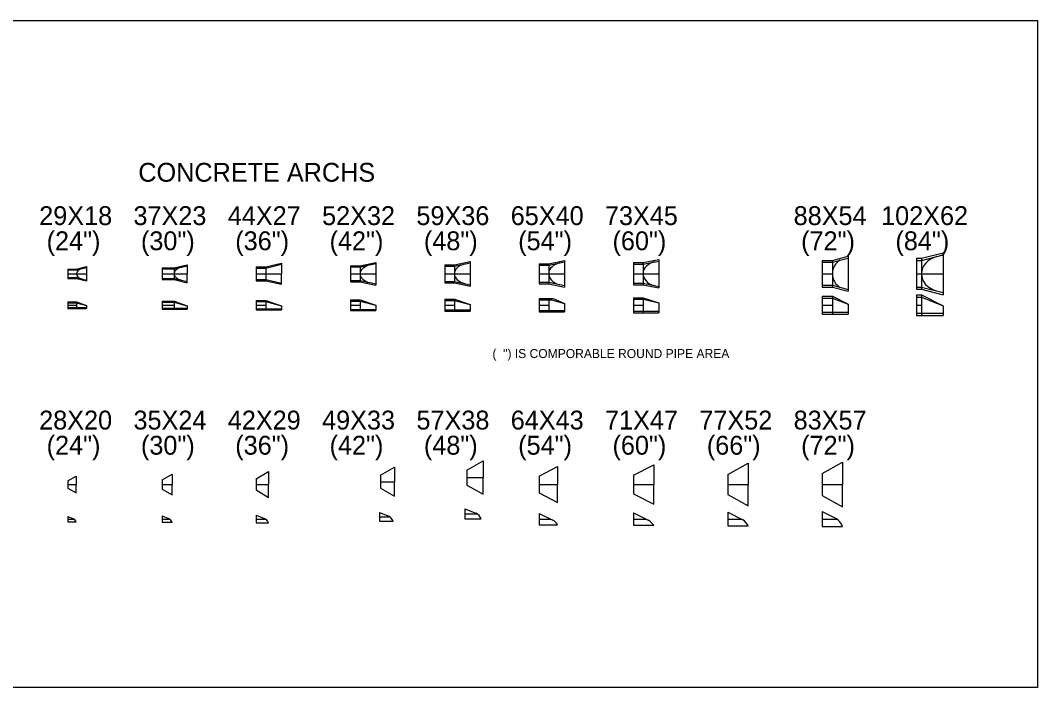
# Model space of a CAD drawing. Extents: x 20500915 to 20506562, y 7965868 to 7970770.
# Drawn here: x 20501230.9 to 20501554.5, y 7966058.6 to 7966270.8 of the extents above; entities that cross this region are included whole.
import ezdxf

# ---------------------------------------------------------------- set-up
doc = ezdxf.new("R2010")
doc.units = 0
doc.layers.add('brgPreStructureNew', color=7, linetype='Continuous')

msp = doc.modelspace()

# ---------------------------------------------------------------- linework, layer by layer
at = {"layer": 'brgPreStructureNew'}
for p, q in [((20501398.93, 7966193.4), (20501403.93, 7966194.44)), ((20501403.93, 7966194.44), (20501403.93, 7966186.02)), ((20501428.93, 7966193.77), (20501433.93, 7966194.73)), ((20501433.93, 7966194.73), (20501433.93, 7966185.73)), ((20501485.93, 7966194.48), (20501485.93, 7966185.98)), ((20501485.93, 7966194.48), (20501489.18, 7966194.48)), ((20501489.18, 7966194.48), (20501494.18, 7966195.81)), ((20501489.18, 7966193.9), (20501494.18, 7966195.23)), ((20501489.18, 7966194.48), (20501489.18, 7966185.98)), ((20501494.18, 7966195.81), (20501494.18, 7966184.65)), ((20501515.93, 7966195.15), (20501515.93, 7966185.31)), ((20501515.93, 7966195.15), (20501517.52, 7966195.15)), ((20501515.93, 7966194.48), (20501517.52, 7966194.48)), ((20501517.52, 7966195.15), (20501524.43, 7966196.9)), ((20501517.52, 7966194.48), (20501524.43, 7966196.23)), ((20501517.52, 7966195.15), (20501517.52, 7966185.31)), ((20501524.43, 7966196.9), (20501524.43, 7966183.56)), ((20501245.93, 7966191.73), (20501248.68, 7966191.73)), ((20501245.93, 7966191.73), (20501245.93, 7966188.73)), ((20501245.93, 7966191.44), (20501248.68, 7966191.44)), ((20501248.68, 7966191.73), (20501251.93, 7966192.52)), ((20501248.68, 7966191.44), (20501251.93, 7966192.23)), ((20501251.93, 7966192.52), (20501251.93, 7966187.94)), ((20501275.93, 7966192.1), (20501275.93, 7966188.36)), ((20501275.93, 7966192.1), (20501279.77, 7966192.1)), ((20501275.93, 7966191.77), (20501279.77, 7966191.77)), ((20501279.77, 7966192.1), (20501283.93, 7966193.06)), ((20501279.77, 7966191.77), (20501283.93, 7966192.73)), ((20501279.77, 7966192.1), (20501279.77, 7966188.36)), ((20501283.93, 7966193.06), (20501283.93, 7966190.23)), ((20501305.93, 7966192.44), (20501305.93, 7966188.02)), ((20501305.93, 7966192.44), (20501308.93, 7966192.44)), ((20501305.93, 7966192.06), (20501308.93, 7966192.06)), ((20501308.93, 7966192.44), (20501313.93, 7966193.58)), ((20501308.93, 7966192.06), (20501313.93, 7966193.23)), ((20501308.93, 7966192.44), (20501308.93, 7966188.02)), ((20501313.93, 7966193.58), (20501313.93, 7966190.23)), ((20501335.93, 7966192.77), (20501335.93, 7966187.69)), ((20501335.93, 7966192.77), (20501338.93, 7966192.77)), ((20501335.93, 7966192.4), (20501338.93, 7966192.4)), ((20501338.93, 7966192.77), (20501343.93, 7966193.86)), ((20501338.93, 7966192.4), (20501343.93, 7966193.48)), ((20501338.93, 7966192.77), (20501338.93, 7966187.69)), ((20501343.93, 7966193.86), (20501343.93, 7966186.61)), ((20501365.93, 7966193.11), (20501365.93, 7966187.36)), ((20501365.93, 7966193.11), (20501368.93, 7966193.11)), ((20501365.93, 7966192.69), (20501368.93, 7966192.69)), ((20501368.93, 7966193.11), (20501373.93, 7966194.15)), ((20501368.93, 7966192.69), (20501373.93, 7966193.73)), ((20501368.93, 7966193.11), (20501368.93, 7966187.36)), ((20501373.93, 7966194.15), (20501373.93, 7966186.31)), ((20501395.93, 7966193.4), (20501395.93, 7966187.06)), ((20501395.93, 7966193.4), (20501398.93, 7966193.4)), ((20501395.93, 7966192.94), (20501398.93, 7966192.94)), ((20501398.93, 7966192.94), (20501403.93, 7966193.98)), ((20501398.93, 7966193.4), (20501398.93, 7966187.06)), ((20501425.93, 7966193.77), (20501425.93, 7966186.69)), ((20501425.93, 7966193.77), (20501428.93, 7966193.77)), ((20501425.93, 7966193.27), (20501428.93, 7966193.27)), ((20501428.93, 7966193.27), (20501433.93, 7966194.23)), ((20501428.93, 7966193.77), (20501428.93, 7966186.69)), ((20501485.93, 7966193.9), (20501489.18, 7966193.9)), ((20501245.93, 7966190.23), (20501251.93, 7966190.23)), ((20501245.93, 7966189.02), (20501248.68, 7966189.02)), ((20501245.93, 7966188.73), (20501248.68, 7966188.73)), ((20501248.68, 7966189.02), (20501251.93, 7966188.23)), ((20501248.68, 7966188.73), (20501251.93, 7966187.94)), ((20501275.93, 7966190.23), (20501283.93, 7966190.23)), ((20501275.93, 7966188.69), (20501279.77, 7966188.69)), ((20501275.93, 7966188.36), (20501279.77, 7966188.36)), ((20501279.77, 7966188.69), (20501283.93, 7966187.73)), ((20501279.77, 7966188.36), (20501283.93, 7966187.4)), ((20501283.93, 7966187.4), (20501283.93, 7966190.23)), ((20501305.93, 7966190.23), (20501313.93, 7966190.23)), ((20501305.93, 7966188.4), (20501308.93, 7966188.4)), ((20501305.93, 7966188.02), (20501308.93, 7966188.02)), ((20501308.93, 7966188.4), (20501313.93, 7966187.23)), ((20501308.93, 7966188.02), (20501313.93, 7966186.88)), ((20501313.93, 7966186.88), (20501313.93, 7966190.23)), ((20501335.93, 7966190.23), (20501343.93, 7966190.23)), ((20501335.93, 7966188.06), (20501338.93, 7966188.06)), ((20501338.93, 7966188.06), (20501343.93, 7966186.98)), ((20501365.93, 7966190.23), (20501373.93, 7966190.23)), ((20501395.93, 7966190.23), (20501403.93, 7966190.23)), ((20501425.93, 7966190.23), (20501433.93, 7966190.23)), ((20501485.93, 7966190.23), (20501489.18, 7966190.23)), ((20501515.93, 7966190.23), (20501524.43, 7966190.23)), ((20501335.93, 7966187.69), (20501338.93, 7966187.69)), ((20501338.93, 7966187.69), (20501343.93, 7966186.61)), ((20501365.93, 7966187.77), (20501368.93, 7966187.77)), ((20501365.93, 7966187.36), (20501368.93, 7966187.36)), ((20501368.93, 7966187.77), (20501373.93, 7966186.73)), ((20501368.93, 7966187.36), (20501373.93, 7966186.31)), ((20501395.93, 7966187.52), (20501398.93, 7966187.52)), ((20501395.93, 7966187.06), (20501398.93, 7966187.06)), ((20501398.93, 7966187.52), (20501403.93, 7966186.48)), ((20501398.93, 7966187.06), (20501403.93, 7966186.02)), ((20501425.93, 7966187.19), (20501428.93, 7966187.19)), ((20501425.93, 7966186.69), (20501428.93, 7966186.69)), ((20501428.93, 7966187.19), (20501433.93, 7966186.23)), ((20501428.93, 7966186.69), (20501433.93, 7966185.73)), ((20501485.93, 7966186.56), (20501489.18, 7966186.56)), ((20501485.93, 7966185.98), (20501489.18, 7966185.98)), ((20501489.18, 7966186.56), (20501494.18, 7966185.23)), ((20501489.18, 7966185.98), (20501494.18, 7966184.65)), ((20501515.93, 7966185.98), (20501517.52, 7966185.98)), ((20501515.93, 7966185.31), (20501517.52, 7966185.31)), ((20501517.52, 7966185.98), (20501524.43, 7966184.23)), ((20501517.52, 7966185.31), (20501524.43, 7966183.56)), ((20501275.93, 7966181.52), (20501275.93, 7966178.94)), ((20501275.93, 7966181.52), (20501279.77, 7966181.52)), ((20501279.77, 7966181.52), (20501279.77, 7966178.94)), ((20501279.77, 7966181.52), (20501283.93, 7966180.07)), ((20501305.93, 7966181.73), (20501305.93, 7966178.73)), ((20501305.93, 7966181.73), (20501308.93, 7966181.73)), ((20501305.93, 7966181.36), (20501308.93, 7966181.36)), ((20501308.93, 7966181.73), (20501308.93, 7966178.73)), ((20501308.93, 7966181.73), (20501313.93, 7966180.03)), ((20501308.93, 7966181.36), (20501313.93, 7966180.03)), ((20501335.93, 7966181.94), (20501335.93, 7966178.52)), ((20501335.93, 7966181.94), (20501338.93, 7966181.94)), ((20501335.93, 7966181.56), (20501338.93, 7966181.56)), ((20501338.93, 7966181.94), (20501343.93, 7966180.22)), ((20501338.93, 7966181.56), (20501338.93, 7966178.52)), ((20501338.93, 7966181.56), (20501343.93, 7966180.22)), ((20501365.93, 7966182.15), (20501365.93, 7966178.31)), ((20501365.93, 7966182.15), (20501368.93, 7966182.15)), ((20501365.93, 7966181.73), (20501368.93, 7966181.73)), ((20501368.93, 7966182.15), (20501368.93, 7966178.31)), ((20501368.93, 7966182.15), (20501373.93, 7966180.48)), ((20501368.93, 7966181.73), (20501373.93, 7966180.48)), ((20501395.93, 7966182.36), (20501395.93, 7966178.11)), ((20501395.93, 7966182.36), (20501400.27, 7966182.36)), ((20501395.93, 7966181.9), (20501399.86, 7966181.9)), ((20501398.93, 7966182.36), (20501398.93, 7966178.11)), ((20501399.86, 7966181.9), (20501403.93, 7966180.78)), ((20501400.35, 7966182.36), (20501403.93, 7966180.78)), ((20501425.93, 7966182.61), (20501425.93, 7966177.86)), ((20501425.93, 7966182.61), (20501428.93, 7966182.61)), ((20501425.93, 7966182.11), (20501428.93, 7966182.11)), ((20501428.93, 7966182.61), (20501428.93, 7966177.86)), ((20501428.93, 7966182.61), (20501433.93, 7966180.94)), ((20501428.93, 7966182.11), (20501433.93, 7966180.94)), ((20501485.93, 7966183.06), (20501485.93, 7966177.4)), ((20501485.93, 7966183.06), (20501489.18, 7966183.06)), ((20501485.93, 7966182.48), (20501489.18, 7966182.48)), ((20501489.18, 7966183.06), (20501489.18, 7966177.4)), ((20501489.18, 7966183.06), (20501494.18, 7966180.56)), ((20501489.18, 7966182.48), (20501494.18, 7966180.56)), ((20501515.93, 7966183.48), (20501515.93, 7966176.98)), ((20501515.93, 7966183.48), (20501517.52, 7966183.48)), ((20501515.93, 7966182.81), (20501517.52, 7966182.81)), ((20501517.52, 7966183.48), (20501517.52, 7966176.98)), ((20501517.52, 7966183.48), (20501524.43, 7966180.02)), ((20501517.52, 7966182.81), (20501524.43, 7966180.02)), ((20501245.93, 7966181.27), (20501248.68, 7966181.27)), ((20501245.93, 7966181.27), (20501245.93, 7966179.19)), ((20501245.93, 7966180.98), (20501248.68, 7966180.98)), ((20501245.93, 7966180.23), (20501248.68, 7966180.23)), ((20501245.93, 7966179.48), (20501251.93, 7966179.48)), ((20501245.93, 7966179.19), (20501251.93, 7966179.19)), ((20501248.68, 7966181.27), (20501251.93, 7966180.19)), ((20501248.68, 7966181.27), (20501248.68, 7966179.19)), ((20501248.68, 7966180.98), (20501251.93, 7966180.19)), ((20501251.93, 7966180.19), (20501251.93, 7966179.19)), ((20501275.93, 7966181.19), (20501279.77, 7966181.19)), ((20501275.93, 7966180.23), (20501279.77, 7966180.23)), ((20501275.93, 7966179.27), (20501283.93, 7966179.27)), ((20501275.93, 7966178.94), (20501283.93, 7966178.94)), ((20501279.77, 7966181.19), (20501283.93, 7966180.07)), ((20501283.93, 7966180.07), (20501283.93, 7966178.94)), ((20501305.93, 7966180.23), (20501308.93, 7966180.23)), ((20501305.93, 7966179.11), (20501313.93, 7966179.11)), ((20501305.93, 7966178.73), (20501313.93, 7966178.73)), ((20501313.93, 7966180.03), (20501313.93, 7966178.73)), ((20501335.93, 7966180.23), (20501338.93, 7966180.23)), ((20501335.93, 7966178.9), (20501338.93, 7966178.9)), ((20501335.93, 7966178.52), (20501338.93, 7966178.52)), ((20501338.93, 7966178.9), (20501343.93, 7966178.9)), ((20501338.93, 7966178.52), (20501343.93, 7966178.52)), ((20501343.93, 7966180.22), (20501343.93, 7966178.52)), ((20501365.93, 7966180.23), (20501368.93, 7966180.23)), ((20501365.93, 7966178.73), (20501368.93, 7966178.73)), ((20501365.93, 7966178.31), (20501368.93, 7966178.31)), ((20501368.93, 7966178.73), (20501373.93, 7966178.73)), ((20501368.93, 7966178.31), (20501373.93, 7966178.31)), ((20501373.93, 7966180.48), (20501373.93, 7966178.31)), ((20501395.93, 7966180.23), (20501398.93, 7966180.23)), ((20501395.93, 7966178.56), (20501399.94, 7966178.56)), ((20501395.93, 7966178.11), (20501400.11, 7966178.11)), ((20501399.94, 7966178.56), (20501403.93, 7966178.56)), ((20501400.11, 7966178.11), (20501403.93, 7966178.11)), ((20501403.93, 7966180.78), (20501403.93, 7966178.11)), ((20501425.93, 7966180.23), (20501428.93, 7966180.23)), ((20501425.93, 7966178.36), (20501428.93, 7966178.36)), ((20501428.93, 7966178.36), (20501433.93, 7966178.36)), ((20501433.93, 7966180.94), (20501433.93, 7966177.86)), ((20501485.93, 7966180.23), (20501489.18, 7966180.23)), ((20501494.18, 7966180.56), (20501494.18, 7966177.4)), ((20501515.93, 7966180.23), (20501517.52, 7966180.23)), ((20501524.43, 7966180.02), (20501524.43, 7966176.98)), ((20501425.93, 7966177.86), (20501428.93, 7966177.86)), ((20501428.93, 7966177.86), (20501433.93, 7966177.86)), ((20501485.93, 7966177.98), (20501489.18, 7966177.98)), ((20501485.93, 7966177.4), (20501489.18, 7966177.4)), ((20501489.18, 7966177.98), (20501494.18, 7966177.98)), ((20501489.18, 7966177.4), (20501494.18, 7966177.4)), ((20501515.93, 7966177.65), (20501517.52, 7966177.65)), ((20501515.93, 7966176.98), (20501517.52, 7966176.98)), ((20501517.52, 7966177.65), (20501524.43, 7966177.65)), ((20501517.52, 7966176.98), (20501524.43, 7966176.98)), ((20501372.91, 7966127.8), (20501378.08, 7966130.72)), ((20501378.08, 7966130.72), (20501378.08, 7966125.43)), ((20501455.93, 7966126.44), (20501462.35, 7966129.98)), ((20501462.35, 7966129.98), (20501462.35, 7966123.23)), ((20501485.93, 7966126.69), (20501492.35, 7966130.36)), ((20501492.35, 7966130.36), (20501492.35, 7966123.23)), ((20501275.93, 7966124.69), (20501279.18, 7966126.56)), ((20501279.18, 7966126.56), (20501279.18, 7966123.23)), ((20501305.93, 7966124.98), (20501309.76, 7966127.36)), ((20501309.76, 7966127.36), (20501309.76, 7966123.23)), ((20501345.42, 7966126.16), (20501349.83, 7966128.74)), ((20501349.83, 7966128.74), (20501349.83, 7966124.11)), ((20501372.91, 7966127.8), (20501372.91, 7966123.05)), ((20501395.93, 7966125.9), (20501401.68, 7966128.98)), ((20501401.68, 7966128.98), (20501401.68, 7966123.23)), ((20501425.93, 7966126.19), (20501432.35, 7966129.52)), ((20501432.35, 7966129.52), (20501432.35, 7966123.23)), ((20501455.93, 7966126.44), (20501455.93, 7966120.02)), ((20501485.93, 7966126.69), (20501485.93, 7966119.77)), ((20501245.93, 7966124.4), (20501248.6, 7966125.9)), ((20501245.93, 7966124.4), (20501245.93, 7966122.06)), ((20501245.93, 7966123.23), (20501248.6, 7966123.23)), ((20501248.6, 7966125.9), (20501248.6, 7966123.23)), ((20501248.6, 7966120.56), (20501248.6, 7966123.23)), ((20501275.93, 7966124.69), (20501275.93, 7966121.77)), ((20501275.93, 7966123.23), (20501279.18, 7966123.23)), ((20501279.18, 7966119.9), (20501279.18, 7966123.23)), ((20501305.93, 7966124.98), (20501305.93, 7966121.48)), ((20501305.93, 7966123.23), (20501309.76, 7966123.23)), ((20501309.76, 7966119.11), (20501309.76, 7966123.23)), ((20501345.42, 7966126.16), (20501345.42, 7966122.07)), ((20501345.42, 7966124.11), (20501349.83, 7966124.11)), ((20501349.83, 7966119.49), (20501349.83, 7966124.11)), ((20501372.91, 7966125.43), (20501378.08, 7966125.43)), ((20501378.08, 7966120.14), (20501378.08, 7966125.43)), ((20501395.93, 7966125.9), (20501395.93, 7966120.56)), ((20501395.93, 7966123.23), (20501401.68, 7966123.23)), ((20501401.68, 7966117.48), (20501401.68, 7966123.23)), ((20501425.93, 7966126.19), (20501425.93, 7966120.27)), ((20501425.93, 7966123.23), (20501432.35, 7966123.23)), ((20501432.35, 7966116.94), (20501432.35, 7966123.23)), ((20501455.93, 7966123.23), (20501462.35, 7966123.23)), ((20501462.35, 7966116.48), (20501462.35, 7966123.23)), ((20501485.93, 7966123.23), (20501492.35, 7966123.23)), ((20501492.35, 7966116.11), (20501492.35, 7966123.23)), ((20501245.93, 7966122.06), (20501248.6, 7966120.56)), ((20501275.93, 7966121.77), (20501279.18, 7966119.9)), ((20501305.93, 7966121.48), (20501309.76, 7966119.11)), ((20501345.42, 7966122.07), (20501349.83, 7966119.49)), ((20501372.91, 7966123.05), (20501378.08, 7966120.14)), ((20501395.93, 7966120.56), (20501401.68, 7966117.48)), ((20501425.93, 7966120.27), (20501432.35, 7966116.94)), ((20501455.93, 7966120.02), (20501462.35, 7966116.48)), ((20501485.93, 7966119.77), (20501492.35, 7966116.11)), ((20501305.93, 7966113.44), (20501305.93, 7966111.02)), ((20501305.93, 7966113.44), (20501308.43, 7966112.44)), ((20501345.09, 7966114.35), (20501345.09, 7966111.6)), ((20501345.09, 7966114.35), (20501347.59, 7966113.35)), ((20501372.26, 7966115.47), (20501372.26, 7966112.31)), ((20501372.26, 7966115.47), (20501375.73, 7966114.08)), ((20501372.26, 7966113.89), (20501376.12, 7966113.89)), ((20501395.93, 7966114.02), (20501395.93, 7966110.44)), ((20501395.93, 7966114.02), (20501400.21, 7966111.88)), ((20501425.93, 7966114.19), (20501425.93, 7966110.27)), ((20501425.93, 7966114.19), (20501430.59, 7966111.86)), ((20501455.93, 7966114.4), (20501455.93, 7966110.06)), ((20501455.93, 7966114.4), (20501460.7, 7966112.02)), ((20501485.93, 7966114.61), (20501485.93, 7966109.86)), ((20501485.93, 7966114.61), (20501490.33, 7966112.41)), ((20501245.93, 7966113.06), (20501245.93, 7966111.4)), ((20501245.93, 7966113.06), (20501247.56, 7966112.41)), ((20501245.93, 7966112.23), (20501247.87, 7966112.23)), ((20501245.93, 7966111.4), (20501248.6, 7966111.4)), ((20501275.93, 7966113.23), (20501275.93, 7966111.23)), ((20501275.93, 7966113.23), (20501278.04, 7966112.39)), ((20501275.93, 7966112.23), (20501278.31, 7966112.23)), ((20501275.93, 7966111.23), (20501279.18, 7966111.23)), ((20501305.93, 7966112.23), (20501308.83, 7966112.23)), ((20501305.93, 7966111.02), (20501309.76, 7966111.02)), ((20501345.09, 7966112.97), (20501348.21, 7966112.97)), ((20501345.09, 7966111.6), (20501349.5, 7966111.6)), ((20501372.26, 7966112.31), (20501377.42, 7966112.31)), ((20501395.93, 7966112.23), (20501399.52, 7966112.23)), ((20501395.93, 7966110.44), (20501401.68, 7966110.44)), ((20501425.93, 7966112.23), (20501429.85, 7966112.23)), ((20501425.93, 7966110.27), (20501432.35, 7966110.27)), ((20501455.93, 7966112.23), (20501460.27, 7966112.23)), ((20501485.93, 7966112.23), (20501490.62, 7966112.23)), ((20501455.93, 7966110.06), (20501462.35, 7966110.06)), ((20501485.93, 7966109.86), (20501492.35, 7966109.86))]:
    msp.add_line(p, q, dxfattribs=at)
msp.add_lwpolyline([(20500915.17, 7966270.8), (20501554.47, 7966270.8), (20501554.47, 7966058.64), (20500915.17, 7966058.64)], close=True, dxfattribs=at)
for centre, radius, start, end in [((20501494.18, 7966190.23), 5, 119.8557, 240.1443), ((20501374.61, 7966111.32), 2.98, 19.3212, 67.9747), ((20501246.51, 7966110.3), 2.36, 27.7999, 63.7435), ((20501276.82, 7966110.04), 2.64, 26.7139, 62.4576), ((20501307.56, 7966110.28), 2.33, 18.5594, 67.8529), ((20501345.46, 7966109.09), 4.76, 31.7729, 63.4421), ((20501398.92, 7966109.1), 3.07, 25.9019, 65.1898), ((20501428.28, 7966107.53), 4.9, 33.9679, 61.9791), ((20501458.56, 7966108.53), 4.09, 22.0609, 58.4869), ((20501488.31, 7966108.73), 4.19, 15.5448, 61.2381)]:
    msp.add_arc(centre, radius, start, end, dxfattribs=at)
for centre, major_axis, ratio, start_param, end_param in [((20501524.43, 7966190.23), (6.92, 0), 0.825892, 1.876172, 4.402684), ((20501251.93, 7966190.23), (3.25, 0), 0.56441, 2.039314, 4.244804), ((20501283.93, 7966190.23), (4.17, 0), 0.553152, 2.002656, 4.256657), ((20501343.93, 7966190.23), (5, 0), 0.612657, 1.972753, 4.315207), ((20501373.93, 7966190.23), (5, 0), 0.663215, 1.931438, 4.362765), ((20501403.93, 7966190.23), (5, 0), 0.720353, 1.84961, 4.37216), ((20501433.93, 7966190.23), (5, 0), 0.775843, 1.831288, 4.416311)]:
    msp.add_ellipse(centre, major_axis=major_axis, ratio=ratio, start_param=start_param, end_param=end_param, dxfattribs=at)

# ---------------------------------------------------------------- texts
for s, height, p in [('CONCRETE ARCHS', 6, (20501268.39, 7966219.49)), ('29X18', 6, (20501236.87, 7966205.71)), ('37X23', 6, (20501266.85, 7966205.71)), ('44X27', 6, (20501296.85, 7966205.71)), ('52X32', 6, (20501326.85, 7966205.71)), ('59X36', 6, (20501356.85, 7966205.71)), ('65X40', 6, (20501386.85, 7966205.71)), ('73X45', 6, (20501416.82, 7966205.71)), ('88X54', 6, (20501476.85, 7966205.71)), ('102X62', 6, (20501504.67, 7966205.71)), ('(24")', 6, (20501239.23, 7966197.71)), ('(30")', 6, (20501269.23, 7966197.71)), ('(36")', 6, (20501299.23, 7966197.71)), ('(42")', 6, (20501329.23, 7966197.71)), ('(48")', 6, (20501359.23, 7966197.71)), ('(54")', 6, (20501389.23, 7966197.71)), ('(60")', 6, (20501419.23, 7966197.71)), ('(72")', 6, (20501479.23, 7966197.71)), ('(84")', 6, (20501509.23, 7966197.71)), ('(  ") IS COMPORABLE ROUND PIPE AREA', 2.8698, (20501381.04, 7966163.43)), ('28X20', 6, (20501236.85, 7966140.71)), ('35X24', 6, (20501266.85, 7966140.71)), ('42X29', 6, (20501296.85, 7966140.71)), ('49X33', 6, (20501326.85, 7966140.71)), ('57X38', 6, (20501356.87, 7966140.71)), ('64X43', 6, (20501386.85, 7966140.71)), ('71X47', 6, (20501416.85, 7966140.71)), ('77X52', 6, (20501446.85, 7966140.71)), ('83X57', 6, (20501476.85, 7966140.71)), ('(24")', 6, (20501239.23, 7966132.71)), ('(30")', 6, (20501269.23, 7966132.71)), ('(36")', 6, (20501299.23, 7966132.71)), ('(42")', 6, (20501329.23, 7966132.71)), ('(48")', 6, (20501359.23, 7966132.71)), ('(54")', 6, (20501389.23, 7966132.71)), ('(60")', 6, (20501419.23, 7966132.71)), ('(66")', 6, (20501449.23, 7966132.71)), ('(72")', 6, (20501479.23, 7966132.71))]:
    msp.add_text(s, height=height, dxfattribs=at).set_placement(p)

doc.saveas('drawing.dxf')
